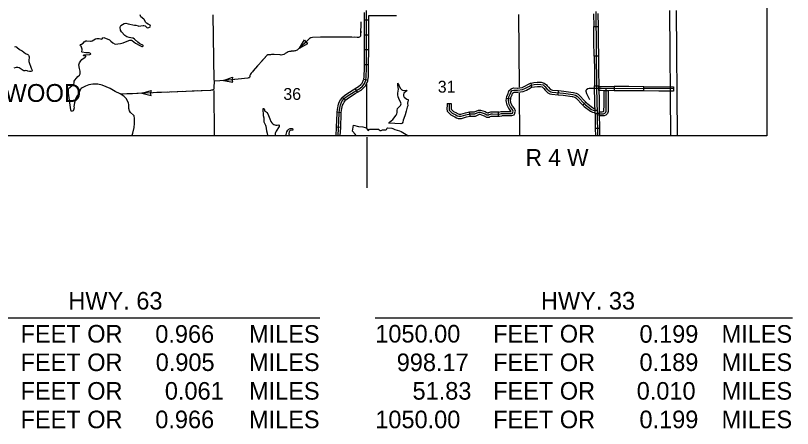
# Model space of a CAD drawing. Extents: x 982240 to 1103002, y 974866 to 1054902.
# Drawn here: x 1037189 to 1064746, y 977168 to 991826 of the extents above; entities that cross this region are included whole.
import ezdxf

# ---------------------------------------------------------------- set-up
doc = ezdxf.new("R2010")
doc.units = 0
for name, color, linetype in [('10', 7, 'Continuous'), ('31', 7, 'Continuous'), ('32', 7, 'Continuous'), ('35', 7, 'Continuous'), ('4', 7, 'Continuous'), ('43', 7, 'Continuous'), ('45', 7, 'Continuous'), ('5', 7, 'Continuous'), ('9', 7, 'Continuous'), ('R_Dimension', 7, 'Continuous'), ('R_Draft', 7, 'Continuous')]:
    doc.layers.add(name, color=color, linetype=linetype)

msp = doc.modelspace()

# ---------------------------------------------------------------- linework, layer by layer
at = {"layer": '10'}
for points in [[(1060387, 992005), (1060415, 987556)], [(1060665, 987556), (1060637, 992006)]]:
    msp.add_lwpolyline(points, dxfattribs=at)
at = {"layer": '31'}
for p, q in [((1057694, 991892), (1057700, 991437)), ((1057844, 991894), (1057850, 991439)), ((1057700, 991437), (1057850, 991439)), ((1057862, 990383), (1057712, 990381)), ((1057862, 990383), (1057862, 990383)), ((1057725, 989326), (1057875, 989327)), ((1057725, 989326), (1057725, 989326)), ((1057878, 989161), (1057875, 989311)), ((1058418, 989307), (1058417, 989157)), ((1058065, 989169), (1058215, 989168)), ((1059473, 989150), (1059474, 989300)), ((1059474, 989300), (1059474, 989300)), ((1060530, 989292), (1060529, 989142)), ((1057896, 988342), (1057746, 988339)), ((1057896, 988261), (1057894, 988410)), ((1057897, 988261), (1057896, 988261))]:
    msp.add_line(p, q, dxfattribs=at)
for points in [[(1057767, 991966), (1057800, 989237), (1057819, 988343)], [(1057706, 990909), (1057700, 991437)], [(1057850, 991439), (1057856, 990911)], [(1057712, 990381), (1057706, 990909)], [(1057856, 990911), (1057862, 990383)], [(1057712, 990381), (1057719, 989854)], [(1057862, 990383), (1057869, 989855)], [(1057869, 989855), (1057875, 989327)], [(1057719, 989854), (1057725, 989326)], [(1057736, 988797), (1057726, 989236), (1057725, 989326)], [(1057875, 989327), (1057876, 989238), (1057886, 988800)], [(1057875, 989311), (1057964, 989311), (1058418, 989307)], [(1058946, 989304), (1058418, 989307)], [(1059474, 989300), (1058946, 989304)], [(1057964, 989237), (1057536, 989236), (1057490, 989225), (1057436, 989193), (1057416, 989163), (1057415, 989136), (1057440, 989058), (1057546, 988845)], [(1057862, 988337), (1057997, 988337), (1058049, 988342), (1058087, 988358), (1058122, 988391), (1058135, 988427), (1058139, 989230)], [(1058417, 989157), (1057964, 989161), (1057878, 989161)], [(1060530, 989219), (1057964, 989237)], [(1058062, 988641), (1058065, 989169)], [(1058215, 989168), (1058212, 988640)], [(1058945, 989154), (1058417, 989157)], [(1059473, 989150), (1058945, 989154)], [(1060001, 989146), (1059473, 989150)], [(1059474, 989300), (1060002, 989296)], [(1060529, 989142), (1060001, 989146)], [(1060002, 989296), (1060530, 989292)], [(1057746, 988342), (1057736, 988797)], [(1057886, 988800), (1057896, 988345)], [(1057894, 988411), (1057993, 988410), (1058030, 988414), (1058046, 988421), (1058058, 988432), (1058061, 988440), (1058062, 988641)], [(1058212, 988640), (1058211, 988414), (1058188, 988347), (1058129, 988293), (1058069, 988267), (1058001, 988260), (1057897, 988261)]]:
    msp.add_lwpolyline(points, dxfattribs=at)
at = {"layer": '32'}
for p, q in [((1049716, 991822), (1050171, 991826)), ((1049716, 991659), (1049716, 991822)), ((1049716, 991659), (1049566, 991659)), ((1049715, 991131), (1049565, 991131)), ((1049715, 990603), (1049565, 990603)), ((1049714, 990075), (1049564, 990075)), ((1049687, 989537), (1049539, 989560)), ((1049315, 989104), (1049238, 989233)), ((1048898, 988825), (1048783, 988920)), ((1048745, 988375), (1048596, 988392)), ((1048722, 987853), (1048572, 987859)), ((1057901, 987816), (1057751, 987814))]:
    msp.add_line(p, q, dxfattribs=at)
for points in [[(1048636, 987556), (1048668, 988356), (1048682, 988479), (1048718, 988660), (1048739, 988714), (1048780, 988797), (1048857, 988890), (1048953, 988965), (1049202, 989123), (1049401, 989241), (1049493, 989319), (1049542, 989378), (1049565, 989413), (1049612, 989529), (1049631, 989654), (1049640, 989959), (1049643, 991895), (1049633, 992007)], [(1049566, 991659), (1049566, 991892), (1049563, 991932)], [(1050171, 991826), (1050699, 991830)], [(1049565, 991131), (1049566, 991659)], [(1049715, 991131), (1049716, 991659)], [(1049565, 990603), (1049565, 991131)], [(1049715, 990603), (1049715, 991131)], [(1049564, 990075), (1049565, 990603)], [(1049714, 990075), (1049715, 990603)], [(1049539, 989560), (1049555, 989661), (1049564, 989960), (1049564, 990075)], [(1049687, 989537), (1049705, 989647), (1049714, 989957), (1049714, 990075)], [(1049238, 989233), (1049356, 989304), (1049439, 989373), (1049481, 989423), (1049497, 989449), (1049537, 989549), (1049539, 989560)], [(1049315, 989104), (1049443, 989181), (1049546, 989266), (1049602, 989334), (1049631, 989380), (1049683, 989509), (1049687, 989537)], [(1048783, 988920), (1048803, 988945), (1048909, 989027), (1049162, 989188), (1049238, 989233)], [(1048898, 988825), (1048909, 988837), (1048995, 988904), (1049241, 989060), (1049315, 989104)], [(1048596, 988392), (1048607, 988491), (1048645, 988681), (1048668, 988745), (1048715, 988839), (1048783, 988920)], [(1048745, 988375), (1048755, 988468), (1048789, 988640), (1048806, 988685), (1048842, 988756), (1048898, 988825)], [(1048572, 987859), (1048592, 988362), (1048596, 988392)], [(1048722, 987853), (1048742, 988350), (1048745, 988375)], [(1057746, 988338), (1057751, 987814)], [(1057819, 988343), (1057831, 987556)], [(1057896, 988341), (1057901, 987816)], [(1048559, 987556), (1048572, 987859)], [(1048709, 987556), (1048722, 987853)], [(1057751, 987814), (1057755, 987556)], [(1057901, 987816), (1057905, 987556)]]:
    msp.add_lwpolyline(points, dxfattribs=at)
at = {"layer": '35'}
for points in [[(1050430, 988000), (1050439, 988023), (1050452, 988040), (1050576, 988137), (1050685, 988291), (1050710, 988337), (1050721, 988386), (1050725, 988457), (1050737, 988522), (1050756, 988550), (1050842, 988631), (1050857, 988653), (1050863, 988689), (1050858, 988723), (1050780, 988883), (1050763, 988934), (1050753, 989009), (1050754, 989071), (1050767, 989213), (1050747, 989348), (1050748, 989425), (1050765, 989417), (1050781, 989353), (1050837, 989246), (1050862, 989216), (1050888, 989192), (1050915, 989177), (1050959, 989166), (1051051, 989179), (1051065, 989170), (1051055, 989139), (1050974, 989085), (1050965, 989073), (1050950, 989006), (1050954, 988974), (1050978, 988928), (1051018, 988891), (1051066, 988861), (1051115, 988841), (1051116, 988823), (1051092, 988714), (1051103, 988618), (1051082, 988577), (1051067, 988527), (1051040, 988434), (1051011, 988304), (1050959, 988169), (1050943, 988115), (1050925, 988036), (1050906, 988005), (1050887, 987989), (1050860, 987983)], [(1046144, 987556), (1046141, 987583), (1046122, 987638), (1046097, 987725), (1046093, 987830), (1046080, 987890), (1046064, 987920), (1046013, 988038), (1046004, 988105), (1046009, 988178), (1045986, 988268), (1045967, 988523), (1045989, 988530), (1046007, 988509), (1046037, 988431), (1046053, 988414), (1046078, 988403), (1046105, 988382), (1046134, 988340), (1046208, 988155), (1046250, 988062), (1046277, 988021), (1046311, 987983), (1046349, 987953), (1046416, 987931), (1046448, 987931), (1046473, 987938), (1046530, 987946), (1046544, 987930), (1046536, 987891), (1046428, 987727), (1046408, 987679), (1046400, 987634), (1046397, 987587), (1046392, 987556)], [(1049147, 987725), (1049180, 987932)], [(1049180, 987931), (1049358, 987890), (1049504, 987880), (1049593, 987855), (1049625, 987838), (1049660, 987791), (1049682, 987757), (1049703, 987747), (1049714, 987748), (1049741, 987787), (1049755, 987798), (1049943, 987797), (1050060, 987791), (1050089, 987770), (1050117, 987744), (1050137, 987739), (1050159, 987742), (1050201, 987764), (1050324, 987773), (1050343, 987780), (1050374, 987826), (1050400, 987844), (1050542, 987827), (1050569, 987817), (1050637, 987780), (1050812, 987737), (1050872, 987715), (1051100, 987573), (1051109, 987559), (1051110, 987556)], [(1050860, 987983), (1050430, 988000)], [(1049272, 987556), (1049235, 987613), (1049147, 987725)]]:
    msp.add_lwpolyline(points, dxfattribs=at)
at = {"layer": '4'}
msp.add_lwpolyline([(1049637, 989395), (1049637, 989349), (1049641, 987810)], dxfattribs=at)
at = {"layer": '43'}
for p, q in [((1047256, 990672), (1047439, 990962)), ((1047439, 990962), (1047482, 990882)), ((1047256, 990672), (1047560, 990832)), ((1047560, 990832), (1047482, 990881)), ((1044561, 989517), (1044882, 989639)), ((1044882, 989639), (1044868, 989549)), ((1044561, 989517), (1044900, 989462)), ((1044900, 989462), (1044868, 989548)), ((1041668, 989065), (1041996, 989168)), ((1041668, 989065), (1042003, 988990)), ((1041996, 989168), (1041976, 989079)), ((1042003, 988990), (1041976, 989078))]:
    msp.add_line(p, q, dxfattribs=at)
for points in [[(1049436, 991600), (1049429, 991137), (1049422, 991097), (1049418, 991080), (1049407, 991061), (1049393, 991052), (1049357, 991048), (1049303, 991051)], [(1049436, 991600), (1049433, 991402)], [(1049431, 991270), (1049429, 991137), (1049422, 991097), (1049418, 991080), (1049407, 991061), (1049393, 991052), (1049357, 991048), (1049303, 991051), (1049227, 991053)], [(1049303, 991051), (1049123, 991055), (1048966, 991056), (1048856, 991057), (1048689, 991055), (1048005, 991054), (1047724, 991041), (1047677, 991037), (1047649, 991030), (1047628, 991018), (1047608, 990998), (1047179, 990599), (1047148, 990582), (1047122, 990572), (1047099, 990568), (1047064, 990563), (1046953, 990554), (1046901, 990544), (1046857, 990532), (1046827, 990518), (1046795, 990499), (1046755, 990474), (1046727, 990457), (1046701, 990441), (1046659, 990426), (1046612, 990421), (1046578, 990431), (1046359, 990444), (1046264, 990437), (1046228, 990432), (1046195, 990431), (1046168, 990431), (1046140, 990430), (1046100, 990409), (1045617, 989867), (1045593, 989833), (1045571, 989803), (1045549, 989778), (1045526, 989744), (1045512, 989716), (1045504, 989696), (1045496, 989675), (1045494, 989656), (1045489, 989632), (1045479, 989620), (1045451, 989609), (1045423, 989605), (1044620, 989523)], [(1048039, 991054), (1048005, 991054), (1047724, 991041), (1047677, 991037), (1047649, 991030), (1047645, 991028)], [(1048567, 991055), (1048171, 991054)], [(1049095, 991055), (1048966, 991056), (1048856, 991057), (1048699, 991055)], [(1047547, 990941), (1047256, 990672)], [(1046137, 990429), (1046100, 990409), (1045865, 990144)], [(1046662, 990427), (1046659, 990426), (1046612, 990421), (1046578, 990431), (1046359, 990444), (1046268, 990438)], [(1046962, 990555), (1046953, 990554), (1046901, 990544), (1046857, 990532), (1046827, 990518), (1046795, 990499), (1046778, 990488)], [(1047156, 990587), (1047148, 990582), (1047122, 990572), (1047099, 990568), (1047064, 990563), (1046962, 990555)], [(1045777, 990046), (1045617, 989867), (1045593, 989833), (1045571, 989803), (1045549, 989778), (1045526, 989744), (1045525, 989741)], [(1045479, 989620), (1045451, 989609), (1045423, 989605), (1045087, 989571)], [(1044620, 989523), (1044238, 989491), (1044226, 989277), (1044223, 989253), (1044222, 989235), (1044218, 989217), (1044216, 989209), (1044211, 989203), (1044197, 989191), (1044186, 989186), (1044171, 989181), (1044161, 989178), (1044152, 989177), (1044142, 989177), (1044108, 989170), (1040913, 989033)], [(1044238, 989485), (1044226, 989288)], [(1044430, 989507), (1044238, 989491), (1044238, 989485)], [(1044955, 989557), (1044620, 989523), (1044561, 989518)], [(1041009, 989037), (1040913, 989033)], [(1041339, 989051), (1041141, 989042)], [(1041536, 989059), (1041339, 989051)], [(1042064, 989082), (1041668, 989065)], [(1042591, 989105), (1042196, 989088)], [(1043119, 989127), (1042723, 989110)], [(1043646, 989150), (1043251, 989133)], [(1044173, 989182), (1044171, 989181), (1044161, 989178), (1044152, 989177), (1044142, 989177), (1044108, 989170), (1043778, 989156)]]:
    msp.add_lwpolyline(points, dxfattribs=at)
at = {"layer": '45'}
for p, q in [((1055502, 989282), (1055476, 989430)), ((1056435, 989010), (1056447, 989159)), ((1054752, 988858), (1054603, 988876)), ((1052495, 988709), (1052645, 988709)), ((1057312, 988643), (1057421, 988747)), ((1053318, 988256), (1053291, 988403)), ((1054320, 988252), (1054323, 988402))]:
    msp.add_line(p, q, dxfattribs=at)
for points in [[(1052570, 988709), (1052570, 988641), (1052565, 988515), (1052574, 988466), (1052678, 988358), (1052804, 988299), (1052858, 988268), (1052907, 988250), (1052993, 988250), (1053164, 988304), (1053312, 988331), (1053384, 988331), (1053438, 988331), (1053483, 988331), (1053625, 988394), (1053670, 988394), (1053742, 988376), (1053845, 988331), (1053908, 988299), (1053962, 988299), (1053980, 988299), (1053994, 988308), (1054039, 988326), (1054057, 988331), (1054102, 988331), (1054345, 988326), (1054421, 988344), (1054462, 988349), (1054779, 988349), (1054818, 988361), (1054833, 988394), (1054842, 988427), (1054818, 988487), (1054749, 988568), (1054698, 988667), (1054671, 988811), (1054686, 988934), (1054734, 989039), (1054752, 989111), (1054809, 989162), (1054866, 989180), (1054989, 989177), (1055175, 989201), (1055283, 989249), (1055421, 989321), (1055481, 989354), (1055583, 989372), (1055697, 989384), (1055823, 989381), (1055901, 989360), (1055967, 989306), (1056033, 989228), (1056111, 989147), (1056171, 989120), (1056222, 989103), (1056627, 989069), (1056951, 989022), (1057052, 988995), (1057106, 988968), (1057403, 988657), (1057619, 988495), (1057673, 988468), (1057740, 988461), (1057817, 988468)], [(1054990, 989253), (1055154, 989274), (1055250, 989317), (1055385, 989387), (1055455, 989426), (1055476, 989430)], [(1055476, 989430), (1055572, 989447), (1055694, 989459), (1055833, 989456), (1055936, 989429), (1056019, 989360), (1056041, 989334)], [(1055502, 989282), (1055593, 989298), (1055700, 989309), (1055812, 989307), (1055866, 989292), (1055914, 989253), (1055926, 989238)], [(1056041, 989334), (1056088, 989279), (1056155, 989210), (1056198, 989190), (1056237, 989177), (1056447, 989159)], [(1054603, 988876), (1054612, 988955), (1054662, 989064), (1054684, 989152), (1054771, 989229), (1054855, 989256), (1054985, 989252), (1054990, 989253)], [(1054752, 988858), (1054759, 988913), (1054805, 989014), (1054819, 989071), (1054847, 989096), (1054876, 989105), (1054992, 989102), (1055009, 989104)], [(1055009, 989104), (1055195, 989128), (1055315, 989182), (1055456, 989255), (1055506, 989283), (1055502, 989282)], [(1055926, 989238), (1055977, 989178), (1056067, 989085), (1056143, 989050), (1056206, 989029), (1056435, 989010)], [(1056447, 989159), (1056635, 989144), (1056966, 989095), (1056984, 989091)], [(1056984, 989091), (1057079, 989065), (1057151, 989029), (1057421, 988747)], [(1054761, 988417), (1054762, 988419), (1054763, 988422), (1054752, 988448), (1054686, 988526), (1054626, 988642), (1054595, 988809), (1054603, 988876)], [(1054897, 988355), (1054903, 988368), (1054920, 988431), (1054883, 988526), (1054811, 988610), (1054769, 988692), (1054746, 988813), (1054752, 988858)], [(1056435, 989010), (1056618, 988995), (1056936, 988948), (1056945, 988946)], [(1056945, 988946), (1057025, 988924), (1057061, 988907), (1057312, 988643)], [(1052495, 988709), (1052495, 988643), (1052490, 988510), (1052504, 988430), (1052633, 988296), (1052768, 988233)], [(1052645, 988709), (1052645, 988640), (1052640, 988521), (1052644, 988501), (1052722, 988420), (1052831, 988369)], [(1057312, 988643), (1057353, 988601), (1057579, 988431), (1057652, 988395), (1057745, 988385)], [(1057421, 988747), (1057453, 988713), (1057659, 988559), (1057694, 988541), (1057741, 988537)], [(1052768, 988233), (1052769, 988233), (1052826, 988199), (1052894, 988175), (1053004, 988175), (1053182, 988231), (1053318, 988256)], [(1052831, 988369), (1052838, 988366), (1052890, 988336), (1052920, 988325), (1052981, 988325), (1053146, 988377), (1053291, 988403)], [(1053291, 988403), (1053305, 988406), (1053384, 988406), (1053438, 988406), (1053467, 988406), (1053609, 988469), (1053679, 988469), (1053766, 988447), (1053841, 988415)], [(1053318, 988256), (1053319, 988256), (1053384, 988256), (1053438, 988256), (1053499, 988256), (1053641, 988319), (1053661, 988319), (1053718, 988304), (1053781, 988277)], [(1053781, 988277), (1053814, 988263), (1053891, 988224), (1053962, 988224), (1054003, 988224), (1054029, 988241), (1054062, 988255), (1054066, 988256), (1054101, 988256), (1054320, 988252)], [(1053841, 988415), (1053877, 988399), (1053926, 988374), (1053962, 988374), (1053958, 988374), (1053959, 988375), (1054016, 988398), (1054048, 988406), (1054103, 988406), (1054323, 988402)], [(1054320, 988252), (1054353, 988251), (1054434, 988270), (1054466, 988274), (1054790, 988274), (1054872, 988299), (1054897, 988355)], [(1054323, 988402), (1054337, 988401), (1054409, 988418), (1054458, 988424), (1054764, 988424), (1054761, 988417)]]:
    msp.add_lwpolyline(points, dxfattribs=at)
at = {"layer": '5'}
for points in [[(1044186, 991855), (1044221, 989515)], [(1055030, 991865), (1055051, 989288)], [(1044226, 989170), (1044240, 987556)], [(1055052, 989072), (1055065, 987556)]]:
    msp.add_lwpolyline(points, dxfattribs=at)
at = {"layer": '9'}
for points in [[(1041064, 991120), (1040952, 991246), (1040918, 991302), (1040897, 991402), (1040915, 991447), (1040928, 991467), (1040980, 991507), (1041047, 991541), (1041102, 991549), (1041181, 991535), (1041405, 991487), (1041461, 991481), (1041534, 991455), (1041566, 991449), (1041635, 991455), (1041715, 991477), (1041738, 991474), (1041790, 991456), (1041842, 991401), (1041861, 991391), (1041920, 991404), (1041969, 991430), (1041976, 991453), (1041961, 991479), (1041888, 991515), (1041835, 991552), (1041799, 991587), (1041762, 991678), (1041743, 991698), (1041635, 991783), (1041620, 991811), (1041606, 991855)], [(1039632, 990397), (1039606, 990396), (1039596, 990406), (1039601, 990420), (1039618, 990432), (1039826, 990440), (1039845, 990452), (1039856, 990467), (1039846, 990478), (1039800, 990496), (1039677, 990496), (1039557, 990521), (1039540, 990532), (1039535, 990546), (1039555, 990598), (1039555, 990628), (1039522, 990741), (1039493, 990755), (1039483, 990774), (1039499, 990796), (1039532, 990808), (1039586, 990848), (1039620, 990895), (1039684, 990929), (1039713, 990930), (1039845, 990910), (1039872, 990914), (1039911, 990932), (1040021, 990997), (1040072, 991013), (1040159, 991014), (1040251, 990987), (1040266, 990998), (1040287, 991032), (1040317, 991046), (1040517, 990958), (1040567, 990912), (1040646, 990862), (1040721, 990807), (1040916, 990836), (1041008, 990860), (1041092, 990896), (1041246, 990953), (1041297, 990952), (1041325, 990936), (1041450, 990848), (1041603, 990760), (1041664, 990730), (1041698, 990726), (1041711, 990734), (1041720, 990752), (1041718, 990765), (1041704, 990778), (1041597, 990819), (1041523, 990879), (1041414, 990982), (1041365, 991017), (1041337, 991026), (1041216, 991043), (1041132, 991072), (1041064, 991120)], [(1037168, 990711), (1037197, 990721), (1037216, 990718), (1037239, 990705), (1037325, 990617), (1037430, 990568), (1037541, 990479), (1037626, 990439), (1037644, 990423), (1037664, 990393), (1037675, 990358), (1037673, 990309), (1037662, 990271), (1037659, 990225), (1037665, 990192), (1037745, 989963), (1037784, 989890), (1037783, 989874), (1037763, 989851), (1037727, 989836), (1037687, 989835), (1037623, 989855), (1037604, 989866), (1037559, 989872), (1037517, 989858), (1037485, 989858), (1037455, 989870), (1037358, 989941), (1037319, 989964), (1037271, 989979), (1037210, 989983), (1037126, 989956)], [(1041349, 987650), (1041401, 987855), (1041413, 987997), (1041413, 988175), (1041395, 988260), (1041372, 988293), (1041268, 988389), (1041233, 988448), (1041212, 988525), (1041207, 988665), (1041199, 988716), (1041128, 988868), (1041103, 988897), (1041039, 988954), (1040900, 989043), (1040728, 989127), (1040542, 989233), (1040257, 989349), (1040107, 989386), (1040043, 989392), (1039930, 989386), (1039793, 989362), (1039671, 989323), (1039558, 989258), (1039518, 989230), (1039498, 989207), (1039432, 989075), (1039407, 989021), (1039346, 988934), (1039328, 988894), (1039279, 988732), (1039262, 988600), (1039263, 988550), (1039244, 988465), (1039231, 988445), (1039198, 988428), (1039168, 988429), (1039153, 988483), (1039071, 989065), (1039065, 989188), (1039073, 989228), (1039084, 989249), (1039125, 989287), (1039258, 989385), (1039273, 989440), (1039270, 989468), (1039273, 989494), (1039289, 989529), (1039349, 989607), (1039399, 989660), (1039457, 989712), (1039480, 989756), (1039482, 989788), (1039477, 989855), (1039455, 989943), (1039440, 990074), (1039463, 990141), (1039507, 990217), (1039546, 990265), (1039660, 990344), (1039686, 990373), (1039683, 990395), (1039632, 990397)], [(1041317, 987556), (1041329, 987577), (1041349, 987650)], [(1046765, 987556), (1046787, 987603), (1046814, 987700), (1046846, 987757), (1046880, 987789), (1046933, 987812), (1046983, 987819), (1047016, 987811), (1047030, 987766), (1047025, 987760), (1046935, 987741), (1046915, 987731), (1046903, 987719), (1046895, 987699), (1046888, 987639), (1046890, 987556)]]:
    msp.add_lwpolyline(points, dxfattribs=at)
at = {"layer": 'R_Dimension'}
msp.add_line((1049664, 985711), (1049663, 987511), dxfattribs=at)
at = {"layer": 'R_Draft'}
for p, q in [((1033185, 981091), (1047985, 981091)), ((1049946, 981091), (1064746, 981091))]:
    msp.add_line(p, q, dxfattribs=at)
msp.add_lwpolyline([(1018617, 1018049), (1063840, 1018049), (1063840, 987556), (1018617, 987556)], close=True, dxfattribs=at)
msp.add_lwpolyline([(1018617, 1018049), (1063840, 1018049), (1063840, 987556), (1018617, 987556)], close=True, dxfattribs=at)

# ---------------------------------------------------------------- texts
at = {"layer": '5'}
for s, p in [('31', (1052166, 989089)), ('36', (1046689, 988830))]:
    msp.add_text(s, height=422.4, dxfattribs=at).set_placement(p)
at = {"layer": '9'}
msp.add_text('PECKERWOOD', height=633.6, rotation=360, dxfattribs=at).set_placement((1033304, 988760))
at = {"layer": 'R_Draft'}
for s, height, p in [('R 4 W', 600, (1055282, 986487)), ('HWY. 63', 624, (1039063, 981390)), ('HWY. 33', 624, (1055825, 981390)), ('FEET OR', 624, (1037368, 980219)), ('0.966', 624, (1042146, 980211)), ('MILES', 624, (1045471, 980211)), ('1050.00', 624, (1049949, 980219)), ('FEET OR', 624, (1054129, 980219)), ('0.199', 624, (1059320, 980211)), ('MILES', 624, (1062233, 980211)), ('FEET OR', 624, (1037368, 979205)), ('0.905', 624, (1042161, 979209)), ('MILES', 624, (1045471, 979209)), ('998.17', 624, (1050710, 979205)), ('FEET OR', 624, (1054129, 979205)), ('0.189', 624, (1059320, 979209)), ('MILES', 624, (1062233, 979209)), ('FEET OR', 624, (1037368, 978191)), ('0.061', 624, (1042485, 978191)), ('MILES', 624, (1045471, 978191)), ('51.83', 624, (1051270, 978191)), ('FEET OR', 624, (1054129, 978191)), ('0.010', 624, (1059222, 978191)), ('MILES', 624, (1062233, 978191)), ('FEET OR', 624, (1037368, 977177)), ('0.966', 624, (1042146, 977178)), ('MILES', 624, (1045471, 977178)), ('1050.00', 624, (1049949, 977177)), ('FEET OR', 624, (1054129, 977177)), ('0.199', 624, (1059320, 977178)), ('MILES', 624, (1062233, 977178))]:
    msp.add_text(s, height=height, dxfattribs=at).set_placement(p)

doc.saveas('drawing.dxf')
